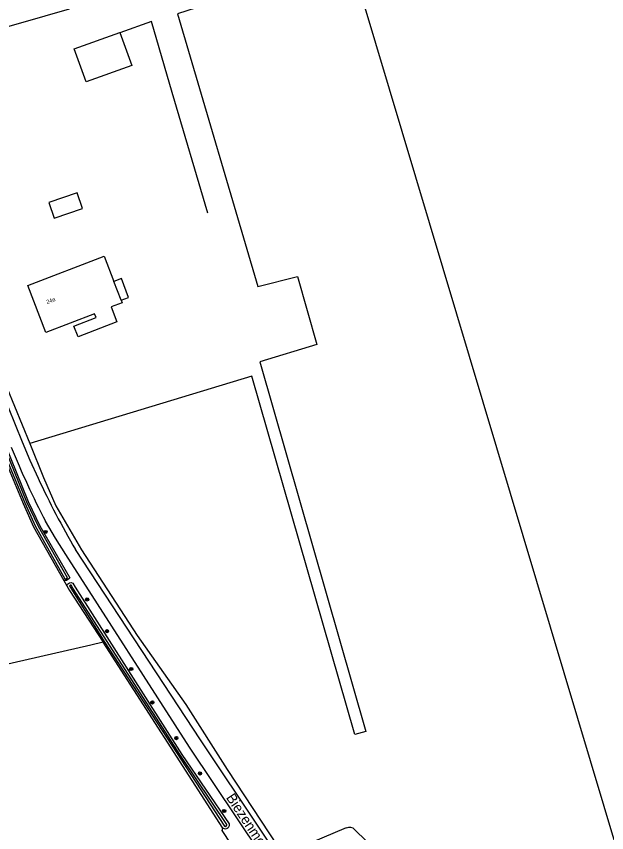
# Model space of a CAD drawing. Extents: x 140000 to 143000, y 403500 to 406000.
# Drawn here: x 140601 to 140748.3, y 405462.4 to 405665.9 of the extents above; entities that cross this region are included whole.
import ezdxf

# ---------------------------------------------------------------- set-up
doc = ezdxf.new("R2010")
doc.units = 0
for name, color, linetype in [('gg-afsc-erfafscheiding', 7, 'Continuous'), ('gg-afsc-hekwerk', 7, 'Continuous'), ('gg-anno-huisnummerreeks BGT', 7, 'Continuous'), ('gg-anno-openbare ruimte label', 7, 'Continuous'), ('gg-bbg-bijgebouw', 7, 'Continuous'), ('gg-bbg-hoofdgebouw', 7, 'Continuous'), ('gg-bbg-luifel en loopbrug', 7, 'Continuous'), ('gg-knt-bronhoudergrens', 7, 'Continuous'), ('gg-knt-verharding', 7, 'Continuous'), ('gg-kntw-bovenkant insteek waterloop', 7, 'Continuous'), ('gg-kntw-waterlijn', 7, 'Continuous'), ('gt-grn-groengrens', 7, 'Continuous'), ('gt-symb-boom', 7, 'Continuous')]:
    doc.layers.add(name, color=color, linetype=linetype)

# ---------------------------------------------------------------- blocks, each defined once
blk = doc.blocks.new('gt0-BOOM')
at = {"layer": 'gt-symb-boom'}
for radius in [0.4, 0.2]:
    blk.add_circle((0, 0), radius, dxfattribs=at)

msp = doc.modelspace()

# ---------------------------------------------------------------- linework, layer by layer
at = {"layer": 'gg-afsc-erfafscheiding'}
msp.add_line((140612.84, 405525.26), (140613.59, 405523.95), dxfattribs=at)
at = {"layer": 'gg-afsc-hekwerk'}
msp.add_line((140602.06, 405664.3), (140614.24, 405667.77), dxfattribs=at)
for points in [[(140583.52, 405659.18), (140586.15, 405659.84), (140602.06, 405664.3)], [(140648.76, 405616.87), (140639.85, 405646.97), (140634.68, 405664.66), (140626.83, 405661.8)]]:
    msp.add_lwpolyline(points, dxfattribs=at)
at = {"layer": 'gg-bbg-bijgebouw'}
msp.add_lwpolyline([(140618.38, 405649.61), (140615.38, 405657.85), (140626.79, 405661.94), (140629.79, 405653.69), (140618.38, 405649.61)], dxfattribs=at)
at = {"layer": 'gg-bbg-hoofdgebouw'}
msp.add_line((140627.11, 405595.14), (140625.32, 405599.81), dxfattribs=at)
msp.add_lwpolyline([(140627.11, 405595.14), (140627.35, 405594.53), (140624.62, 405593.48), (140626.05, 405589.75), (140616.36, 405586.03), (140615.33, 405588.71), (140620.85, 405590.83), (140620.49, 405591.76), (140608.34, 405587.1), (140603.85, 405598.81), (140622.89, 405606.12), (140625.32, 405599.81)], dxfattribs=at)
at = {"layer": 'gg-bbg-luifel en loopbrug'}
for points in [[(140609.06, 405619.55), (140610.41, 405615.59), (140617.51, 405618.02), (140616.12, 405621.96), (140609.06, 405619.55)], [(140627.11, 405595.14), (140628.98, 405595.86), (140627.18, 405600.52), (140625.32, 405599.81)]]:
    msp.add_lwpolyline(points, dxfattribs=at)
at = {"layer": 'gg-knt-bronhoudergrens'}
for p, q in [((140684.24, 405680.52), (140763.52, 405415.94)), ((140598.62, 405573.36), (140604.3, 405559.42))]:
    msp.add_line(p, q, dxfattribs=at)
for points in [[(140668.9, 405675.54), (140641.18, 405666.54), (140661.25, 405598.58), (140671.12, 405601.08), (140675.98, 405584.11), (140661.7, 405579.81), (140688.22, 405487.64), (140685.43, 405486.83), (140659.71, 405576.22), (140604.3, 405559.42)], [(140604.3, 405559.42), (140607.77, 405550.91), (140610.79, 405543.85), (140617.24, 405532.9), (140631.12, 405511.58), (140643.29, 405494.3), (140653.59, 405478.15), (140670.4, 405452.64), (140682.39, 405434.2), (140689.15, 405423.92), (140690.15, 405422.91), (140692.57, 405421.54)], [(140622.6, 405509.85), (140619.57, 405509.16), (140546, 405492.31)]]:
    msp.add_lwpolyline(points, dxfattribs=at)
at = {"layer": 'gg-knt-verharding'}
for points in [[(140597.21, 405572.8), (140602.42, 405559.8), (140604.35, 405555.26), (140606.39, 405550.77)], [(140689.6, 405415.1), (140673.87, 405439.38), (140644.21, 405483.71), (140613.35, 405531.74), (140610.71, 405535.83), (140608.28, 405540.05)], [(140692.73, 405415.93), (140676.87, 405440.7), (140646.95, 405485.52), (140615.72, 405533)]]:
    msp.add_lwpolyline(points, dxfattribs=at)
for centre, radius, start, end in [((140776.37, 405629.35), 190.34, 201.8502, 207.9823), ((140804.98, 405643.69), 219.25, 205.075, 210.3206)]:
    msp.add_arc(centre, radius, start, end, dxfattribs=at)
at = {"layer": 'gg-kntw-bovenkant insteek waterloop'}
for p, q in [((140652.5, 405463.53), (140622.6, 405509.85)), ((140683.3, 405463.54), (140671.69, 405458.64)), ((140692.27, 405456.48), (140685.47, 405463.12))]:
    msp.add_line(p, q, dxfattribs=at)
for points in [[(140575.3, 405616.31), (140585.76, 405589.94), (140587.97, 405584.22), (140603.96, 405544.96), (140606.86, 405538.88), (140614.29, 405525.93), (140614.1, 405525.63), (140613.48, 405525.28), (140613.23, 405525.23), (140612.84, 405525.26)], [(140586.2, 405583.69), (140586.35, 405583.37), (140602.69, 405544.42), (140605.27, 405538.66), (140612.84, 405525.26)], [(140613.59, 405523.95), (140613.74, 405524.32), (140614.27, 405524.69), (140614.63, 405524.74), (140615.07, 405524.57), (140615.61, 405523.63), (140642.29, 405481.84), (140654.12, 405464.59), (140654.11, 405464.11), (140653.81, 405463.62), (140653.56, 405463.42), (140653.18, 405463.27), (140652.5, 405463.53)], [(140613.59, 405523.95), (140614.25, 405522.78), (140622.6, 405509.85)]]:
    msp.add_lwpolyline(points, dxfattribs=at)
msp.add_arc((140684.08, 405461.69), 2, 45.6342, 112.923, dxfattribs=at)
at = {"layer": 'gg-kntw-waterlijn'}
for points in [[(140586.6, 405583.88), (140586.75, 405583.55), (140603.09, 405544.6), (140605.66, 405538.86), (140613.11, 405525.68), (140613.21, 405525.67), (140613.32, 405525.7), (140613.77, 405525.95), (140606.47, 405538.68), (140603.56, 405544.78), (140587.56, 405584.06), (140585.35, 405589.78), (140575.06, 405615.75), (140573.94, 405615.31), (140584.21, 405589.12), (140586.6, 405583.88)], [(140614.5, 405524.12), (140614.27, 405523.96), (140614.76, 405523.09), (140622.88, 405510.03), (140652.89, 405464.03), (140653.18, 405463.92), (140653.25, 405463.94), (140653.35, 405464.02), (140653.51, 405464.28), (140653.52, 405464.41), (140641.91, 405481.59), (140615.1, 405523.32), (140614.65, 405524.09), (140614.56, 405524.12), (140614.5, 405524.12)]]:
    msp.add_lwpolyline(points, dxfattribs=at)
at = {"layer": 'gt-grn-groengrens'}
msp.add_lwpolyline([(140657.67, 405455.52), (140656.98, 405455.88), (140652.33, 405462.95), (140652.5, 405463.53)], dxfattribs=at)

# ---------------------------------------------------------------- block references
at = {"layer": 'gt-symb-boom'}
for p in [(140608.25, 405537.36), (140618.64, 405520.54), (140623.59, 405512.62), (140629.64, 405503.18), (140634.91, 405494.85), (140640.9, 405485.96), (140646.79, 405477.14), (140652.85, 405467.79)]:
    msp.add_blockref('gt0-BOOM', p, dxfattribs=at)

# ---------------------------------------------------------------- texts
at = {"layer": 'gg-anno-huisnummerreeks BGT'}
msp.add_text('24a', height=1, rotation=21, dxfattribs=at).set_placement((140608.66, 405594.17))
at = {"layer": 'gg-anno-openbare ruimte label'}
msp.add_text('Biezenmortelsestraat', height=2.5, rotation=303.7, dxfattribs=at).set_placement((140653.21, 405471.11))

doc.saveas('drawing.dxf')
